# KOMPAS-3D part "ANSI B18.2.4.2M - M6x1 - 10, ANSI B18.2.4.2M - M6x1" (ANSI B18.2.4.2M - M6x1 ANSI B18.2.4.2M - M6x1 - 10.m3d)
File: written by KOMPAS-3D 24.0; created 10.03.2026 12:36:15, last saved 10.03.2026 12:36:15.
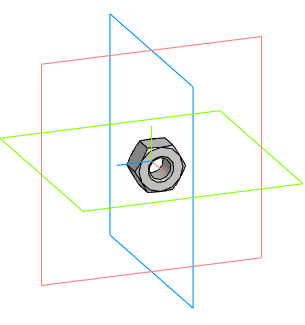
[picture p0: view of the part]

Document properties: Автор: R2D2; Полное имя файла: E:\Работа\Зайцев\BV3232P(4pc)-FP-3WL-F-ISO-H Кран шаровой DN.ru Ду15-100 Ру16\DN40\исходные материалы\ANSI B18.2.4.2M - M6x1 ANSI B18.2.4.2M - M6x1 - 10.m3d

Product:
- Body: Solid1  | qty 1
- Part/product: ANSI B18.2.4.2M - M6x1 - 10  | designation ANSI B18.2.4.2M - M6x1
    Комментарий: Типы метрических   шестигранных гаек   2
    additional columns: Сталь, мягкая

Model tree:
1. Solid1  (labels: Solid1)

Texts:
  ANSI B18.2.4.2M - M6x1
